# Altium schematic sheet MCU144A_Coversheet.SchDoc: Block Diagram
size 431 x 279 mm; Date: Not shown in title block; ApprovedBy: Not shown in title block; CheckedBy: Not shown in title block; Author: Not shown in title block; CompanyName: Not shown in title block; DrawnBy: Gustavo Martinez; Engineer: Not shown in title block; Organization: Not shown in title block; Address1: Not shown in title block; Address2: Not shown in title block; Address3: Not shown in title block; Address4: Not shown in title block; DocumentNumber: 1; Revision: Use project parameter SCH_Rev; SheetNumber: 1; SheetTotal: 8; PageSetup: Record=PageOptions¦CenterHorizontal=True¦CenterVertical=True¦PrintScale=1.00¦XCorrection=1.00¦YCorrection=1.00¦PrintKind=0¦BorderSize=5000000¦LeftOffset=0¦BottomOffset=0¦Orientation=2¦PaperLength=1000¦PaperWidth=1000¦Scale=100¦PaperSource=15¦PrintQuality=600¦MediaType=1¦DitherType=10¦PaperKind=Letter¦PrintScaleMode=1
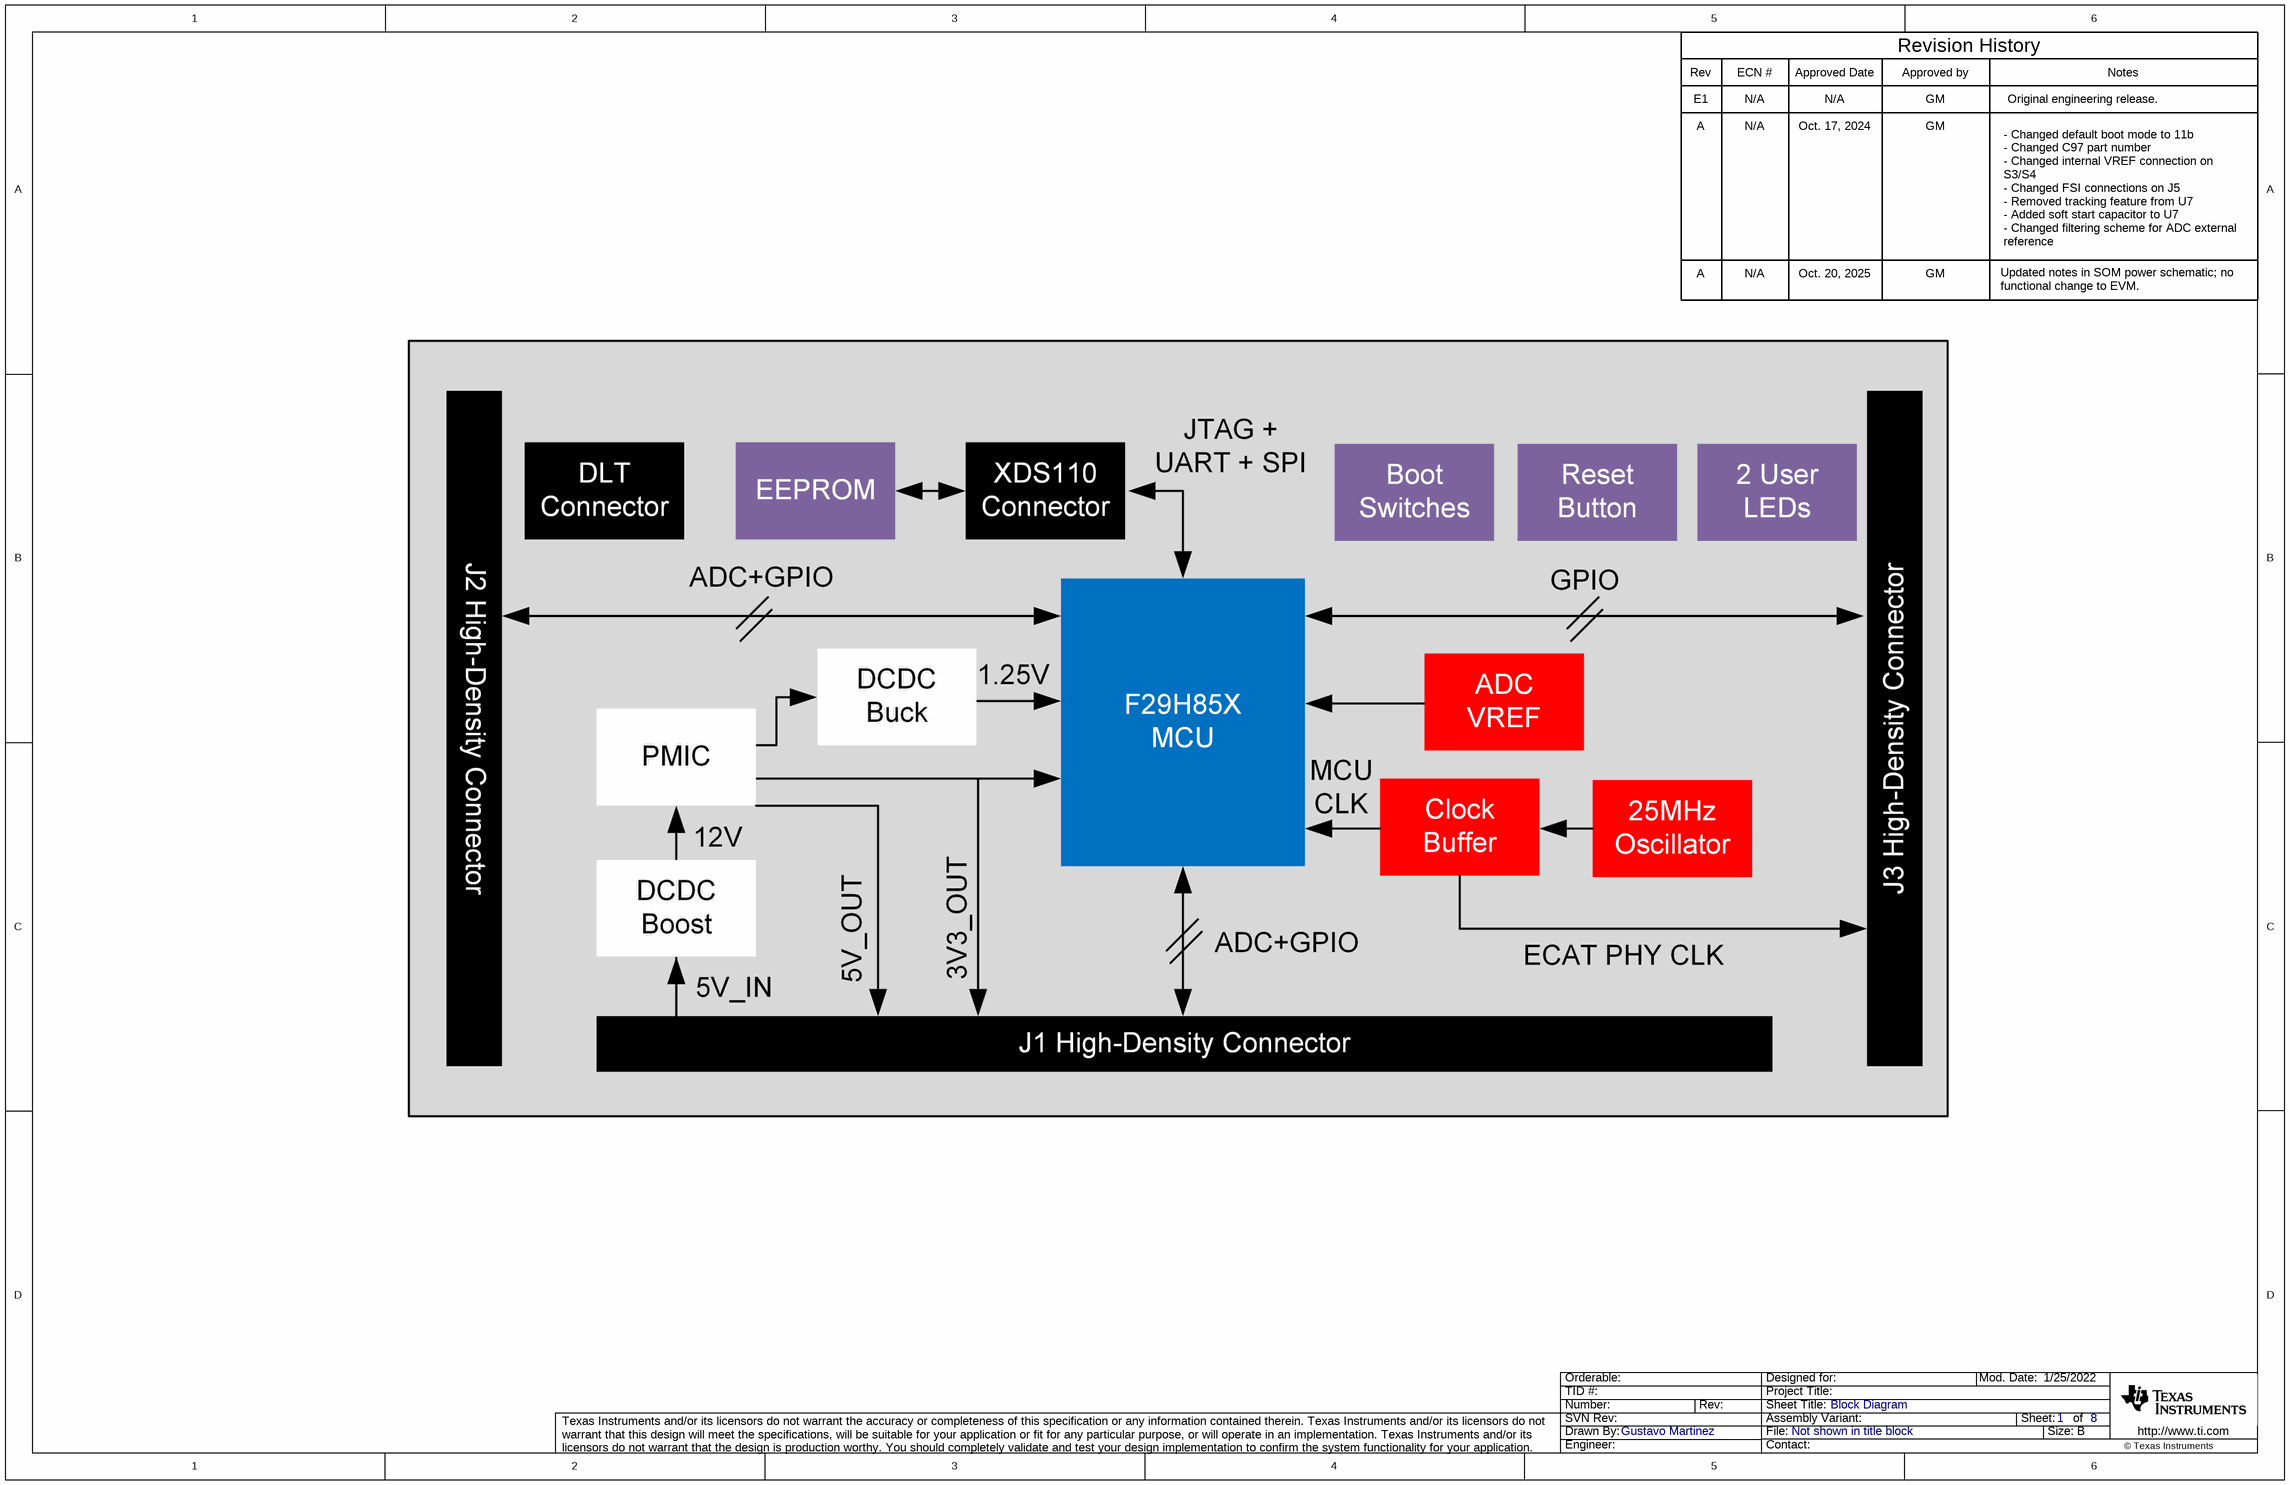
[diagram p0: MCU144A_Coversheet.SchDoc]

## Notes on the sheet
- Rev
- E1
- ECN #
- N/A
- Approved Date
- Approved by
- GM
- Revision History
- Original engineering release.
- Notes
- A
- Oct. 17, 2024
- Oct. 20, 2025
- Updated notes in SOM power schematic; no functional change to EVM.
- - Changed default boot mode to 11b
  - Changed C97 part number
  - Changed internal VREF connection on S3/S4
  - Changed FSI connections on J5
  - Removed tracking feature from U7
  - Added soft start capacitor to U7
  - Changed filtering scheme for ADC external reference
